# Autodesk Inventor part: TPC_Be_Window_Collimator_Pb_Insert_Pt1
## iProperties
Shininess: 64.0
Length Units: 11269
Angle Units: 11279
Time Units: 11290
Mass Units: 11283
Length Display Precision: 3
Angle Display Precision: 2
Compacted: True
Part Number: TPC_Be_Window_Collimator_Pb_Insert_Pt1
Document SubType Name: Modeling
Created: 2004-07
Designer: John Blackburn
Manufacturer: Standard
Standards Organization: Custom
Material: Lead
Density: 0.0
Volumn: 0.0
Area: 0.0
PropertySet Name: Model Information
Control State: 0
Master: False
Checked Out: False
Author: John Blackburn
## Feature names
1. Revolution1
2. Hole1
3. Circular Pattern1
